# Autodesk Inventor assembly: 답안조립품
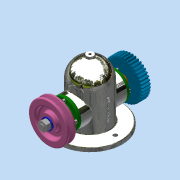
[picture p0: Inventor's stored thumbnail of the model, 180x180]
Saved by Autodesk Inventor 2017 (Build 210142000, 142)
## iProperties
Created: 2019-11
Part Number: 답안조립품
Document SubType Name: Assembly
Designer: 1-17-lg
Author: 1-17-lg
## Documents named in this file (14)
- C:\Users\1-17-lg\Desktop\491104V1011\답안조립품.iam
- C:\Users\1-17-lg\Desktop\491104V1011\본체.ipt
- C:\Users\1-17-lg\Desktop\491104V1011\V-벨트풀리.ipt
- V-벨트풀리.ipt
- C:\Users\1-17-lg\Desktop\491104V1011\너트 M12x1.25.ipt
- C:\Users\1-17-lg\Desktop\491104V1011\베어링 6203.ipt
- C:\Users\1-17-lg\Desktop\491104V1011\볼트 M4.ipt
- C:\Users\1-17-lg\Desktop\491104V1011\부시.ipt
- C:\Users\1-17-lg\Desktop\491104V1011\스퍼기어.ipt
- C:\Users\1-17-lg\Desktop\491104V1011\오일 실 26 38 8.ipt
- C:\Users\1-17-lg\Desktop\491104V1011\와셔 12x24.ipt
- C:\Users\1-17-lg\Desktop\491104V1011\축.ipt
- C:\Users\1-17-lg\Desktop\491104V1011\커버.ipt
- C:\Users\1-17-lg\Desktop\491104V1011\키 5x5x12.ipt
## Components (1 placed, 1 different names)
1. V-벨트풀리:1 — Mate:27, Mate:28, Mate:29, Mate:35
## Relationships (4: Mate 4)
- Mate:27: V-벨트풀리:1
- Mate:28: V-벨트풀리:1
- Mate:29: V-벨트풀리:1
- Mate:35: V-벨트풀리:1
